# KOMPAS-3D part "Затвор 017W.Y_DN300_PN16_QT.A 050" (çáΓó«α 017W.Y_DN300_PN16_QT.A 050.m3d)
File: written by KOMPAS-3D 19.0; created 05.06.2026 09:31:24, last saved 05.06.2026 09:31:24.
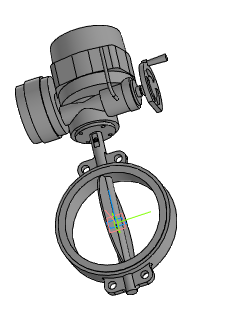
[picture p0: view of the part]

Document properties: Автор: Энергия; Полное имя файла: ..\..\..\3d для проектировщиков\x.x Тип 017W.Y(S) Затвор дисковый поворотный межфланцевый\Затвор 017W.Y(S)_DN32-DN1200_QT.A_MT903.A\Затвор 017W.Y_DN300_PN16_QT.A 050.a3d

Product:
- Part/product: Затвор 017W.Y_DN300_PN16_QT.A 050
    Масса: 140.822

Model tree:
1. Операция без истории:1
